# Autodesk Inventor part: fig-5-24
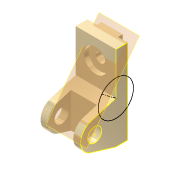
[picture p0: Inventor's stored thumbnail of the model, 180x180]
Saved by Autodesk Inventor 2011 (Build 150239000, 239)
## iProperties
Shininess: 65.0
Angle Display Precision: 2
Document Length Units: 11269
Document Angle Units: 11279
Document Time Units: 11290
Document Mass Units: 11283
Document Length Units Precision: 3
Document Angle Units Precision: 2
Compacted: False
Created: 2001-11
Part Number: fig-5-24
Document SubType Name: Modeling
Designer: Renu Muthoo
Density: 1 g/cm^3
Density: 0.0
Volumn: 0.0
Area: 0.0
PropertySet Name: Model Information
Control State: 0
Master: False
Checked Out: False
Author: Renu Muthoo
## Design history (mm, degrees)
node "Sketch1"
sketch "Sketch2"
  geometry: L1 (33.257, 104.664)-(33.257, -75.336); L2 (33.257, -75.336)-(8.257, -75.336); L3 (8.257, -75.336)-(-45.451, -59.045); L4 (-45.451, -1.628)-(8.257, 14.664); L5 (8.257, 14.664)-(8.257, 104.664); L6 (8.257, 104.664)-(33.257, 104.664); C1 r 15 at (-36.743, -30.336); A1 r 30 centre (-36.743, -30.336) between (-45.451, -1.628) and (-45.451, -59.045)
  constraints: 12 end point, 2 centre point, 2 equal length, 2 parallel, 2 point on circle, 2 tangent, 1 coincident, 1 perpendicular, 1 vertical
  dimensions: "d0" = 180 distance of L1.start L1.end; "d1" = 30 radius of A1; "d2" = 25 distance of L5.end L1.start; "d3" = 45 distance from line of L2 A1.centre; "d4" = 70 distance from line of L1 A1.centre; "d5" = 30 diameter of C1
extrude "Extrusion1" new body sketch "Sketch2" distance "d6" = 85; taper "d7" = 0 deg
workplane "Work Plane1"
sketch "Sketch3"
  geometry: L1 (15, 62.364)-(70, 62.364); L2 (70, 62.364)-(70, -52.386); L3 (70, -52.386)-(15, -52.386); L4 (15, -52.386)-(15, 62.364); L5 (0, -45)-(0, -28.708) reference
  constraints: 8 end point, 2 parallel, 1 horizontal, 1 perpendicular
  dimensions: "d8" = 55 distance of L1.start L1.end; "d9" = 15 distance between parallel lines of L5 L4
extrude "Extrusion2" cut sketch "Sketch3" distance "d10" = 50; taper "d11" = 0 deg
sketch "Sketch4"
  geometry: L1 (0, 25)-(85, 25) reference; L2 (0, 0)-(0, 25) reference; L3 (20, 25)-(65, 25); L4 (65, 25)-(65, 35); L5 (65, 35)-(20, 35); L6 (20, 35)-(20, 25)
  constraints: 8 end point, 2 parallel, 1 horizontal, 1 perpendicular, 1 point on line
  dimensions: "d12" = 45 distance of L4.end L5.end; "d13" = 10 distance of L3.end L4.end; "d14" = 20 distance between parallel lines of L2 L6
extrude "Extrusion3" join sketch "Sketch4" stored distance "d15" = 50; taper "d16" = 0 deg
sketch "Sketch5"
  geometry: L1 (85, 0)-(85, 90) reference; L2 (0, 90)-(85, 90) reference; 1 further point
  dimensions: "d17" = 42 distance from line of L2 point (42.5, 48); "d18" = 42.5 distance from line of L1 point (42.5, 48)
hole "Hole1" sketch "Sketch5" at (42.5, 48) diameter "d19" = 20; stored, may be unused: countersink angle "d23" = 82 deg, drill point angle "d25" = 118 deg; dims "d20" = 6, "d21" = 50, "d22" = 10, "d24" = 8
sketch "Sketch8"
  geometry: L1 (75.336, 33.257)-(75.336, 8.257) reference; L2 (-104.664, 33.257)-(75.336, 33.257) reference; L3 (-104.664, 8.257)-(-104.664, 33.257) reference; L4 (-14.664, 8.257)-(-104.664, 8.257) reference; L5 (1.628, -45.451)-(-14.664, 8.257) reference; L6 (75.336, 8.257)-(59.045, -45.451) reference; C1 r 15 at (30.336, -36.743) reference; C2 r 37.437 at (-14.664, 8.257); A1 r 30 centre (30.336, -36.743) between (1.628, -45.451) and (59.045, -45.451) reference
  constraints: 1 centre point, 1 coincident
sketch "Sketch9"
  geometry: L1 (75.336, 33.257)-(75.336, 8.257) reference; L2 (-14.664, 8.257)-(-104.664, 8.257) reference; L3 (1.628, -45.451)-(-14.664, 8.257) reference; L4 (75.336, 8.257)-(59.045, -45.451) reference; L5 (-14.664, 8.257)-(-37, -21.743); C1 r 15 at (30.336, -36.743) reference; A1 r 30 centre (30.336, -36.743) between (1.628, -45.451) and (59.045, -45.451) reference
  constraints: 2 end point
workplane "Work Plane11"
body "Solid1"
